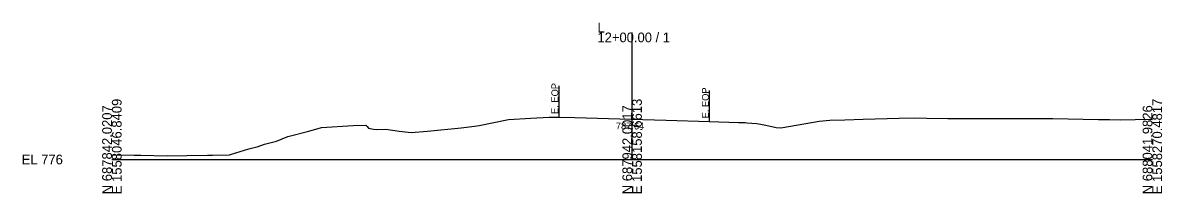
# Model space of a CAD drawing. Extents: x -26 to 2603, y -3010 to 9589.
# Drawn here: x 1274.3 to 1602.8, y -3009.7 to -2960.7 of the extents above; entities that cross this region are included whole.
import ezdxf

# ---------------------------------------------------------------- set-up
doc = ezdxf.new("R2010")
doc.units = 0
for name, color, linetype in [('Default', 7, 'Continuous'), ('Exist Cross Section Cell', 7, 'Continuous'), ('Exist XS Center Line Elevation Label', 7, 'Continuous'), ('Exist XS Ground Line', 7, 'Continuous'), ('Prop XS Label Text', 7, 'Continuous')]:
    doc.layers.add(name, color=color, linetype=linetype)

msp = doc.modelspace()

# ---------------------------------------------------------------- linework, layer by layer
at = {"layer": 'Exist Cross Section Cell'}
for p, q in [((1450, -3000), (1450, -2963.47)), ((1300, -3000), (1450, -3000)), ((1450, -3000), (1600, -3000))]:
    msp.add_line(p, q, dxfattribs=at)
at = {"layer": 'Exist XS Ground Line'}
msp.add_lwpolyline([(1300, -2998.63), (1306.39, -2998.74), (1308.31, -2998.79), (1315.93, -2998.98), (1321.61, -2998.86), (1327.57, -2998.78), (1327.98, -2998.75), (1328.96, -2998.71), (1333.87, -2998.63), (1334.51, -2998.48), (1339.46, -2996.89), (1342.15, -2996.22), (1344, -2995.58), (1347.42, -2994.68), (1350.7, -2993.38), (1356.79, -2991.81), (1360.39, -2990.83), (1369.56, -2990.22), (1373.25, -2990.1), (1373.6, -2990.48), (1373.96, -2990.97), (1375.43, -2991.31), (1376.33, -2991.39), (1378.97, -2991.28), (1382.79, -2991.83), (1386.31, -2992.28), (1390.99, -2991.87), (1400.68, -2990.93), (1404.54, -2990.4), (1405.86, -2990.18), (1414.39, -2988.52), (1420.75, -2988.13), (1426.04, -2987.85), (1427.56, -2987.84), (1428.82, -2987.82), (1433.5, -2987.93), (1449.72, -2988.35), (1459.86, -2988.67), (1472.23, -2989.11), (1480.69, -2989.32), (1482.64, -2989.37), (1483.05, -2989.43), (1485.95, -2989.65), (1488.54, -2990.13), (1491.53, -2990.76), (1492.83, -2990.88), (1495.65, -2990.42), (1503.9, -2989), (1506.99, -2988.73), (1511.33, -2988.58), (1516.58, -2988.37), (1526.98, -2988.11), (1531.39, -2987.98), (1535.01, -2988.09), (1541.02, -2988.16), (1556.09, -2988.21), (1559.59, -2988.18), (1562.54, -2988.18), (1571.3, -2988.22), (1584.44, -2988.45), (1587.63, -2988.51), (1590.77, -2988.55), (1599.29, -2988.44), (1600, -2988.47)], dxfattribs=at)
at = {"layer": 'Prop XS Label Text'}
for p, q in [((1428.82, -2978.82), (1428.82, -2987.82)), ((1472.23, -2980.11), (1472.23, -2989.11))]:
    msp.add_line(p, q, dxfattribs=at)

# ---------------------------------------------------------------- texts
at = {"layer": 'Default'}
msp.add_text('-', height=0.0001, dxfattribs=at).set_placement((1300, -3000))
at = {"layer": 'Exist Cross Section Cell'}
for s, p in [('12+00.00 / 1', (1440, -2966.27)), ('L', (1440, -2963.47)), ('EL 776', (1274, -3001.4))]:
    msp.add_text(s, height=2.8, dxfattribs=at).set_placement(p)
for s, p in [('E 1558046.8409', (1302.8, -3010)), ('E 1558158.6613', (1452.8, -3010)), ('E 1558270.4817', (1602.8, -3010)), ('N 687842.0207', (1300, -3010)), ('N 687942.0017', (1450, -3010)), ('N 688041.9826', (1600, -3010))]:
    msp.add_text(s, height=2.8, rotation=90, dxfattribs=at).set_placement(p)
at = {"layer": 'Exist XS Center Line Elevation Label'}
msp.add_text('787.64', height=2, dxfattribs=at).set_placement((1445.31, -2991.36))
at = {"layer": 'Prop XS Label Text'}
for p in [(1428.72, -2986.9), (1472.13, -2988.18)]:
    msp.add_text('E. EOP', height=2, rotation=90, dxfattribs=at).set_placement(p)

doc.saveas('drawing.dxf')
